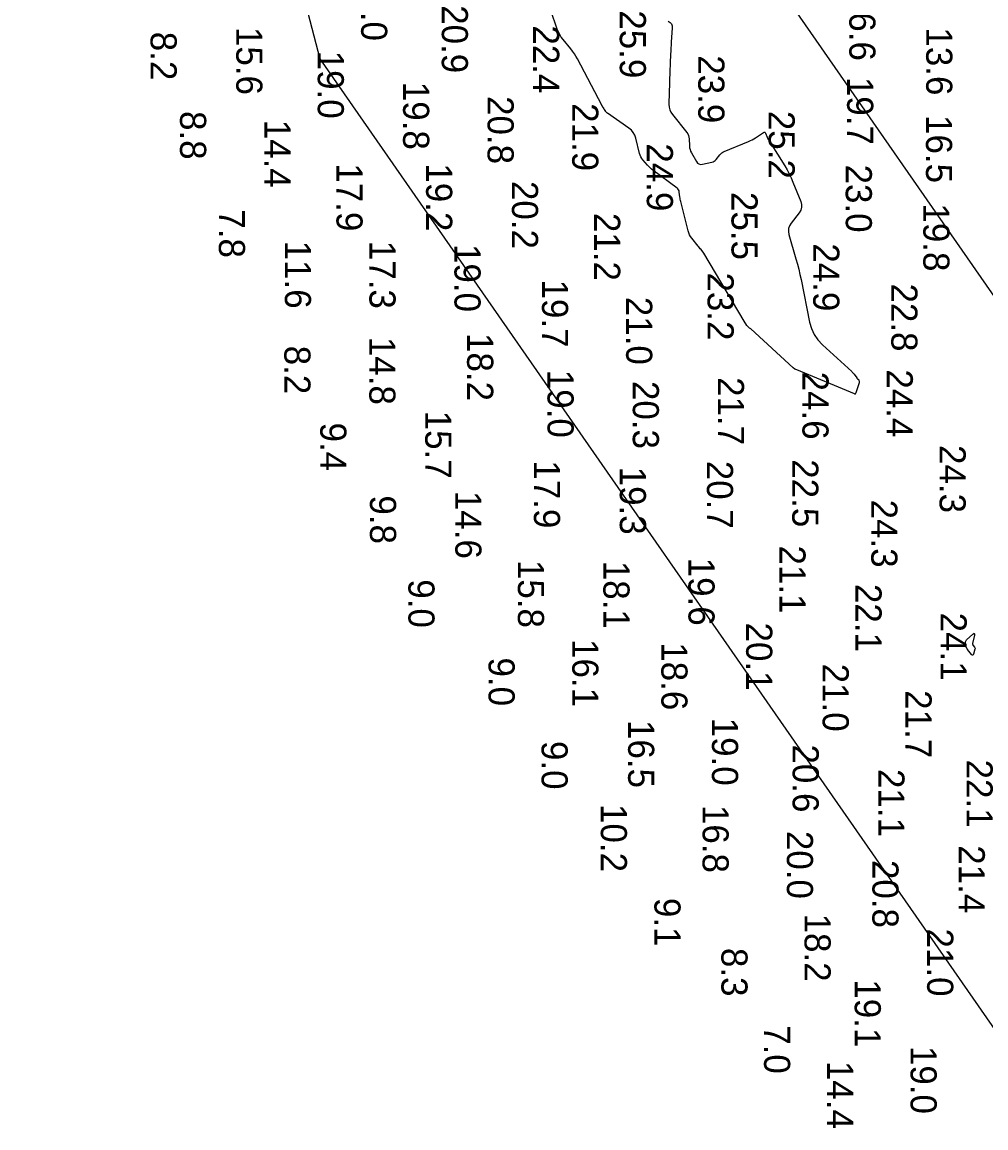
# Model space of a CAD drawing. Extents: x 1178573 to 1187098, y 693282 to 751751.
# Drawn here: x 1182495 to 1182956, y 742692 to 743221 of the extents above; entities that cross this region are included whole.
import ezdxf

# ---------------------------------------------------------------- set-up
doc = ezdxf.new("R2010")
doc.units = 0
for name, color, linetype in [('G-ANNO-PATT', 7, 'Continuous'), ('V-HYDS-MAJR', 7, 'Continuous'), ('V-HYDS-SOUN', 7, 'Continuous')]:
    doc.layers.add(name, color=color, linetype=linetype)

msp = doc.modelspace()

# ---------------------------------------------------------------- linework, layer by layer
at = {"layer": 'G-ANNO-PATT'}
for p, q in [((1182494.83, 743743.62), (1182637.36, 743203.34)), ((1183156.73, 742806.5), (1182821.74, 743288.49)), ((1182750.89, 743217.47), (1182747.88, 743226.33)), ((1182803.92, 743221.31), (1182804.85, 743220.72)), ((1182751.41, 743216.13), (1182750.89, 743217.47)), ((1182752.05, 743214.85), (1182751.41, 743216.13)), ((1182804.85, 743220.72), (1182805.49, 743219.96)), ((1182805.9, 743217.93), (1182805.45, 743211.39)), ((1182805.49, 743219.96), (1182805.84, 743219.03)), ((1182805.84, 743219.03), (1182805.9, 743217.93)), ((1182752.8, 743213.64), (1182752.05, 743214.85)), ((1182753.66, 743212.49), (1182752.8, 743213.64)), ((1182757.35, 743208.03), (1182753.66, 743212.49)), ((1182805.45, 743211.39), (1182805.36, 743209.9)), ((1182758.24, 743206.89), (1182757.35, 743208.03)), ((1182759.07, 743205.72), (1182758.24, 743206.89)), ((1182759.84, 743204.5), (1182759.07, 743205.72)), ((1182805.14, 743205.44), (1182804.66, 743192.78)), ((1182805.2, 743206.93), (1182805.14, 743205.44)), ((1182805.27, 743208.41), (1182805.2, 743206.93)), ((1182805.36, 743209.9), (1182805.27, 743208.41)), ((1182637.36, 743203.34), (1182974.41, 742718.39)), ((1182760.54, 743203.24), (1182759.84, 743204.5)), ((1182772.2, 743181.16), (1182760.54, 743203.24)), ((1182804.56, 743189.99), (1182804.51, 743188.59)), ((1182804.6, 743191.38), (1182804.56, 743189.99)), ((1182804.66, 743192.78), (1182804.6, 743191.38)), ((1182804.47, 743187.19), (1182804.31, 743181.59)), ((1182804.51, 743188.59), (1182804.47, 743187.19)), ((1182772.29, 743180.99), (1182772.2, 743181.16)), ((1182772.39, 743180.81), (1182772.29, 743180.99)), ((1182772.49, 743180.64), (1182772.39, 743180.81)), ((1182772.59, 743180.46), (1182772.49, 743180.64)), ((1182773.01, 743179.78), (1182772.59, 743180.46)), ((1182773.11, 743179.61), (1182773.01, 743179.78)), ((1182773.22, 743179.44), (1182773.11, 743179.61)), ((1182773.32, 743179.27), (1182773.22, 743179.44)), ((1182773.43, 743179.1), (1182773.32, 743179.27)), ((1182774.11, 743178.02), (1182773.43, 743179.1)), ((1182804.31, 743181.59), (1182804.38, 743180.23)), ((1182804.38, 743180.23), (1182804.69, 743178.95)), ((1182804.69, 743178.95), (1182805.22, 743177.74)), ((1182774.27, 743177.8), (1182774.11, 743178.02)), ((1182774.45, 743177.59), (1182774.27, 743177.8)), ((1182774.65, 743177.4), (1182774.45, 743177.59)), ((1182774.87, 743177.24), (1182774.65, 743177.4)), ((1182785.17, 743170.15), (1182774.87, 743177.24)), ((1182805.22, 743177.74), (1182805.98, 743176.61)), ((1182805.98, 743176.61), (1182812.83, 743168.1)), ((1182786.34, 743169.18), (1182785.17, 743170.15)), ((1182787.28, 743168.06), (1182786.34, 743169.18)), ((1182788, 743166.79), (1182787.28, 743168.06)), ((1182812.83, 743168.1), (1182813.3, 743167.4)), ((1182845.69, 743165.52), (1182849.57, 743168.11)), ((1182849.57, 743168.11), (1182849.9, 743168.27)), ((1182849.9, 743168.27), (1182850.18, 743168.27)), ((1182850.18, 743168.27), (1182850.4, 743168.11)), ((1182850.4, 743168.11), (1182850.57, 743167.78)), ((1182788.48, 743165.35), (1182788, 743166.79)), ((1182790.28, 743157.95), (1182788.48, 743165.35)), ((1182813.3, 743167.4), (1182813.65, 743166.66)), ((1182813.65, 743166.66), (1182813.88, 743165.87)), ((1182813.88, 743165.87), (1182813.99, 743165.04)), ((1182813.99, 743165.04), (1182814.15, 743161.6)), ((1182830.76, 743158.97), (1182842.45, 743163.79)), ((1182842.45, 743163.79), (1182843.3, 743164.16)), ((1182843.3, 743164.16), (1182844.11, 743164.57)), ((1182844.11, 743164.57), (1182844.91, 743165.02)), ((1182844.91, 743165.02), (1182845.69, 743165.52)), ((1182850.57, 743167.78), (1182851.25, 743165.85)), ((1182851.25, 743165.85), (1182851.35, 743165.61)), ((1182851.35, 743165.61), (1182851.45, 743165.39)), ((1182851.45, 743165.39), (1182851.57, 743165.17)), ((1182851.57, 743165.17), (1182851.71, 743164.96)), ((1182851.71, 743164.96), (1182852.28, 743164.12)), ((1182852.28, 743164.12), (1182852.42, 743163.91)), ((1182852.42, 743163.91), (1182852.56, 743163.7)), ((1182852.56, 743163.7), (1182852.7, 743163.49)), ((1182852.7, 743163.49), (1182852.83, 743163.28)), ((1182852.83, 743163.28), (1182859.71, 743152.13)), ((1182790.53, 743157.13), (1182790.28, 743157.95)), ((1182814.15, 743161.6), (1182814.24, 743160.75)), ((1182814.24, 743160.75), (1182814.43, 743159.93)), ((1182814.43, 743159.93), (1182814.71, 743159.14)), ((1182814.71, 743159.14), (1182815.09, 743158.38)), ((1182815.09, 743158.38), (1182817.46, 743154.18)), ((1182826.98, 743155.19), (1182828.66, 743157.36)), ((1182828.66, 743157.36), (1182829.1, 743157.87)), ((1182829.1, 743157.87), (1182829.6, 743158.3)), ((1182829.6, 743158.3), (1182830.16, 743158.67)), ((1182830.16, 743158.67), (1182830.76, 743158.97)), ((1182790.88, 743156.36), (1182790.53, 743157.13)), ((1182791.31, 743155.64), (1182790.88, 743156.36)), ((1182791.84, 743154.96), (1182791.31, 743155.64)), ((1182794.12, 743152.35), (1182791.84, 743154.96)), ((1182794.71, 743151.72), (1182794.12, 743152.35)), ((1182817.46, 743154.18), (1182818.01, 743153.45)), ((1182818.01, 743153.45), (1182818.67, 743153)), ((1182818.67, 743153), (1182819.46, 743152.8)), ((1182819.46, 743152.8), (1182820.36, 743152.88)), ((1182820.36, 743152.88), (1182824.79, 743153.82)), ((1182824.79, 743153.82), (1182825.43, 743154.02)), ((1182825.43, 743154.02), (1182826.01, 743154.31)), ((1182826.01, 743154.31), (1182826.52, 743154.7)), ((1182826.52, 743154.7), (1182826.98, 743155.19)), ((1182859.71, 743152.13), (1182860.82, 743150.25)), ((1182795.33, 743151.11), (1182794.71, 743151.72)), ((1182795.98, 743150.55), (1182795.33, 743151.11)), ((1182796.66, 743150.01), (1182795.98, 743150.55)), ((1182808.2, 743141.4), (1182796.66, 743150.01)), ((1182860.82, 743150.25), (1182861.84, 743148.32)), ((1182861.84, 743148.32), (1182862.79, 743146.35)), ((1182808.62, 743141.02), (1182808.2, 743141.4)), ((1182862.79, 743146.35), (1182863.65, 743144.34)), ((1182863.65, 743144.34), (1182867.38, 743135.07)), ((1182808.94, 743140.59), (1182808.62, 743141.02)), ((1182809.16, 743140.1), (1182808.94, 743140.59)), ((1182809.28, 743139.55), (1182809.16, 743140.1)), ((1182809.56, 743137.25), (1182809.28, 743139.55)), ((1182809.64, 743136.67), (1182809.56, 743137.25)), ((1182809.74, 743136.1), (1182809.64, 743136.67)), ((1182809.85, 743135.53), (1182809.74, 743136.1)), ((1182809.99, 743134.97), (1182809.85, 743135.53)), ((1182813.57, 743120.97), (1182809.99, 743134.97)), ((1182867.4, 743130.95), (1182866.63, 743129.68)), ((1182867.38, 743135.07), (1182867.77, 743133.65)), ((1182867.78, 743132.27), (1182867.4, 743130.95)), ((1182867.77, 743133.65), (1182867.78, 743132.27)), ((1182866.63, 743129.68), (1182862.78, 743124.72)), ((1182813.86, 743120.03), (1182813.57, 743120.97)), ((1182861.55, 743122.1), (1182861.46, 743120.7)), ((1182861.46, 743120.7), (1182861.73, 743119.22)), ((1182861.99, 743123.44), (1182861.55, 743122.1)), ((1182862.78, 743124.72), (1182861.99, 743123.44)), ((1182814.24, 743119.15), (1182813.86, 743120.03)), ((1182814.72, 743118.3), (1182814.24, 743119.15)), ((1182815.29, 743117.51), (1182814.72, 743118.3)), ((1182818.31, 743113.72), (1182815.29, 743117.51)), ((1182861.73, 743119.22), (1182865.12, 743107.56)), ((1182818.65, 743113.29), (1182818.31, 743113.72)), ((1182818.99, 743112.87), (1182818.65, 743113.29)), ((1182819.33, 743112.44), (1182818.99, 743112.87)), ((1182819.67, 743112.02), (1182819.33, 743112.44)), ((1182821.02, 743110.32), (1182819.67, 743112.02)), ((1182840.25, 743077.86), (1182821.02, 743110.32)), ((1182865.12, 743107.56), (1182865.8, 743105.11)), ((1182865.8, 743105.11), (1182866.43, 743102.64)), ((1182866.43, 743102.64), (1182867.01, 743100.17)), ((1182867.01, 743100.17), (1182867.54, 743097.67)), ((1182867.54, 743097.67), (1182871.61, 743077.37)), ((1182841.67, 743075.79), (1182840.25, 743077.86)), ((1182842.04, 743075.3), (1182841.67, 743075.79)), ((1182842.47, 743074.86), (1182842.04, 743075.3)), ((1182842.94, 743074.47), (1182842.47, 743074.86)), ((1182843.45, 743074.13), (1182842.94, 743074.47)), ((1182863.77, 743055.44), (1182843.45, 743074.13)), ((1182871.61, 743077.37), (1182872.48, 743074.27)), ((1182872.48, 743074.27), (1182873.8, 743071.42)), ((1182873.8, 743071.42), (1182875.56, 743068.82)), ((1182875.56, 743068.82), (1182877.77, 743066.47)), ((1182877.77, 743066.47), (1182891.77, 743053.73)), ((1182864.5, 743054.89), (1182863.77, 743055.44)), ((1182865.45, 743054.53), (1182864.5, 743054.89)), ((1182893.19, 743042.98), (1182865.45, 743054.53)), ((1182891.77, 743053.73), (1182892.07, 743053.44)), ((1182892.07, 743053.44), (1182892.36, 743053.14)), ((1182892.36, 743053.14), (1182892.63, 743052.82)), ((1182892.63, 743052.82), (1182892.88, 743052.48)), ((1182892.88, 743052.48), (1182894.21, 743050.65)), ((1182895.3, 743048.28), (1182893.7, 743043.48)), ((1182894.21, 743050.65), (1182894.29, 743050.54)), ((1182894.29, 743050.54), (1182894.38, 743050.44)), ((1182894.38, 743050.44), (1182894.48, 743050.35)), ((1182894.48, 743050.35), (1182894.58, 743050.27)), ((1182894.58, 743050.27), (1182895.01, 743049.95)), ((1182895.01, 743049.95), (1182895.11, 743049.87)), ((1182895.11, 743049.87), (1182895.18, 743049.77)), ((1182895.18, 743049.77), (1182895.24, 743049.65)), ((1182895.24, 743049.65), (1182895.26, 743049.53)), ((1182895.26, 743049.53), (1182895.35, 743048.88)), ((1182895.34, 743048.43), (1182895.3, 743048.28)), ((1182895.36, 743048.57), (1182895.34, 743048.43)), ((1182895.35, 743048.88), (1182895.37, 743048.72)), ((1182895.37, 743048.72), (1182895.36, 743048.57)), ((1182893.31, 743042.78), (1182893.19, 743042.98)), ((1182893.48, 743042.94), (1182893.31, 743042.78)), ((1182893.7, 743043.48), (1182893.48, 743042.94)), ((1182946.26, 742924.48), (1182946.34, 742924.8)), ((1182946.34, 742924.8), (1182946.49, 742925.1)), ((1182946.49, 742925.1), (1182946.72, 742925.37)), ((1182946.72, 742925.37), (1182949.67, 742928.1)), ((1182950.49, 742927.64), (1182949.65, 742923.56)), ((1182949.67, 742928.1), (1182950.15, 742928.47)), ((1182950.15, 742928.47), (1182950.45, 742928.52)), ((1182950.45, 742928.52), (1182950.56, 742928.24)), ((1182950.56, 742928.24), (1182950.49, 742927.64)), ((1182946.26, 742924.12), (1182946.26, 742924.48)), ((1182946.49, 742922.17), (1182946.26, 742924.12)), ((1182946.51, 742922.04), (1182946.49, 742922.17)), ((1182946.54, 742921.92), (1182946.51, 742922.04)), ((1182946.59, 742921.8), (1182946.54, 742921.92)), ((1182946.66, 742921.69), (1182946.59, 742921.8)), ((1182946.94, 742921.24), (1182946.66, 742921.69)), ((1182947.01, 742921.13), (1182946.94, 742921.24)), ((1182947.09, 742921.02), (1182947.01, 742921.13)), ((1182947.16, 742920.92), (1182947.09, 742921.02)), ((1182947.24, 742920.81), (1182947.16, 742920.92)), ((1182949.1, 742918.38), (1182947.24, 742920.81)), ((1182949.65, 742923.56), (1182949.63, 742923.32)), ((1182949.63, 742923.32), (1182949.66, 742923.08)), ((1182949.66, 742923.08), (1182949.74, 742922.86)), ((1182949.74, 742922.86), (1182949.89, 742922.66)), ((1182949.89, 742922.66), (1182950.57, 742921.87)), ((1182950.75, 742920.98), (1182950.01, 742918.55)), ((1182950.57, 742921.87), (1182950.7, 742921.67)), ((1182950.7, 742921.67), (1182950.78, 742921.45)), ((1182950.8, 742921.22), (1182950.75, 742920.98)), ((1182950.78, 742921.45), (1182950.8, 742921.22)), ((1182949.38, 742918.09), (1182949.1, 742918.38)), ((1182949.63, 742918.02), (1182949.38, 742918.09)), ((1182949.84, 742918.17), (1182949.63, 742918.02)), ((1182950.01, 742918.55), (1182949.84, 742918.17))]:
    msp.add_line(p, q, dxfattribs=at)
at = {"layer": 'V-HYDS-MAJR'}
msp.add_lwpolyline([(1182803.92, 743221.31), (1182804.85, 743220.72), (1182805.49, 743219.96), (1182805.84, 743219.03), (1182805.9, 743217.93), (1182805.45, 743211.39), (1182805.36, 743209.9), (1182805.27, 743208.41), (1182805.2, 743206.93), (1182805.14, 743205.44), (1182804.66, 743192.78), (1182804.6, 743191.38), (1182804.56, 743189.99), (1182804.51, 743188.59), (1182804.47, 743187.19), (1182804.31, 743181.59), (1182804.38, 743180.23), (1182804.69, 743178.95), (1182805.22, 743177.74), (1182805.98, 743176.61), (1182812.83, 743168.1), (1182813.3, 743167.4), (1182813.65, 743166.66), (1182813.88, 743165.87), (1182813.99, 743165.04), (1182814.15, 743161.6), (1182814.24, 743160.75), (1182814.43, 743159.93), (1182814.71, 743159.14), (1182815.09, 743158.38), (1182817.46, 743154.18), (1182818.01, 743153.45), (1182818.67, 743153), (1182819.46, 743152.8), (1182820.36, 743152.88), (1182824.79, 743153.82), (1182825.43, 743154.02), (1182826.01, 743154.31), (1182826.52, 743154.7), (1182826.98, 743155.19), (1182828.66, 743157.36), (1182829.1, 743157.87), (1182829.6, 743158.3), (1182830.16, 743158.67), (1182830.76, 743158.97), (1182842.45, 743163.79), (1182843.3, 743164.16), (1182844.11, 743164.57), (1182844.91, 743165.02), (1182845.69, 743165.52), (1182849.57, 743168.11), (1182849.9, 743168.27), (1182850.18, 743168.27), (1182850.4, 743168.11), (1182850.57, 743167.78), (1182851.25, 743165.85), (1182851.35, 743165.61), (1182851.45, 743165.39), (1182851.57, 743165.17), (1182851.71, 743164.96), (1182852.28, 743164.12), (1182852.42, 743163.91), (1182852.56, 743163.7), (1182852.7, 743163.49), (1182852.83, 743163.28), (1182859.71, 743152.13), (1182860.82, 743150.25), (1182861.84, 743148.32), (1182862.79, 743146.35), (1182863.65, 743144.34), (1182867.38, 743135.07), (1182867.77, 743133.65), (1182867.78, 743132.27), (1182867.4, 743130.95), (1182866.63, 743129.68), (1182862.78, 743124.72), (1182861.99, 743123.44), (1182861.55, 743122.1), (1182861.46, 743120.7), (1182861.73, 743119.22), (1182865.12, 743107.56), (1182865.8, 743105.11), (1182866.43, 743102.64), (1182867.01, 743100.17), (1182867.54, 743097.67), (1182871.61, 743077.37), (1182872.48, 743074.27), (1182873.8, 743071.42), (1182875.56, 743068.82), (1182877.77, 743066.47), (1182891.77, 743053.73), (1182892.07, 743053.44), (1182892.36, 743053.14), (1182892.63, 743052.82), (1182892.88, 743052.48), (1182894.21, 743050.65), (1182894.29, 743050.54), (1182894.38, 743050.44), (1182894.48, 743050.35), (1182894.58, 743050.27), (1182895.01, 743049.95), (1182895.11, 743049.87), (1182895.18, 743049.77), (1182895.24, 743049.65), (1182895.26, 743049.53), (1182895.35, 743048.88), (1182895.37, 743048.72), (1182895.36, 743048.57), (1182895.34, 743048.43), (1182895.3, 743048.28), (1182893.7, 743043.48), (1182893.48, 743042.94), (1182893.31, 743042.78), (1182893.19, 743042.98), (1182865.45, 743054.53), (1182864.5, 743054.89), (1182863.77, 743055.44), (1182843.45, 743074.13), (1182842.94, 743074.47), (1182842.47, 743074.86), (1182842.04, 743075.3), (1182841.67, 743075.79), (1182840.25, 743077.86), (1182821.02, 743110.32), (1182819.67, 743112.02), (1182819.33, 743112.44), (1182818.99, 743112.87), (1182818.65, 743113.29), (1182818.31, 743113.72), (1182815.29, 743117.51), (1182814.72, 743118.3), (1182814.24, 743119.15), (1182813.86, 743120.03), (1182813.57, 743120.97), (1182809.99, 743134.97), (1182809.85, 743135.53), (1182809.74, 743136.1), (1182809.64, 743136.67), (1182809.56, 743137.25), (1182809.28, 743139.55), (1182809.16, 743140.1), (1182808.94, 743140.59), (1182808.62, 743141.02), (1182808.2, 743141.4), (1182796.66, 743150.01), (1182795.98, 743150.55), (1182795.33, 743151.11), (1182794.71, 743151.72), (1182794.12, 743152.35), (1182791.84, 743154.96), (1182791.31, 743155.64), (1182790.88, 743156.36), (1182790.53, 743157.13), (1182790.28, 743157.95), (1182788.48, 743165.35), (1182788, 743166.79), (1182787.28, 743168.06), (1182786.34, 743169.18), (1182785.17, 743170.15), (1182774.87, 743177.24), (1182774.65, 743177.4), (1182774.45, 743177.59), (1182774.27, 743177.8), (1182774.11, 743178.02), (1182773.43, 743179.1), (1182773.32, 743179.27), (1182773.22, 743179.44), (1182773.11, 743179.61), (1182773.01, 743179.78), (1182772.59, 743180.46), (1182772.49, 743180.64), (1182772.39, 743180.81), (1182772.29, 743180.99), (1182772.2, 743181.16), (1182760.54, 743203.24), (1182759.84, 743204.5), (1182759.07, 743205.72), (1182758.24, 743206.89), (1182757.35, 743208.03), (1182753.66, 743212.49), (1182752.8, 743213.64), (1182752.05, 743214.85), (1182751.41, 743216.13), (1182750.89, 743217.47), (1182747.88, 743226.33)], dxfattribs=at)
msp.add_lwpolyline([(1182946.34, 742924.8), (1182946.49, 742925.1), (1182946.72, 742925.37), (1182949.67, 742928.1), (1182950.15, 742928.47), (1182950.45, 742928.52), (1182950.56, 742928.24), (1182950.49, 742927.64), (1182949.65, 742923.56), (1182949.63, 742923.32), (1182949.66, 742923.08), (1182949.74, 742922.86), (1182949.89, 742922.66), (1182950.57, 742921.87), (1182950.7, 742921.67), (1182950.78, 742921.45), (1182950.8, 742921.22), (1182950.75, 742920.98), (1182950.01, 742918.55), (1182949.84, 742918.17), (1182949.63, 742918.02), (1182949.38, 742918.09), (1182949.1, 742918.38), (1182947.24, 742920.81), (1182947.16, 742920.92), (1182947.09, 742921.02), (1182947.01, 742921.13), (1182946.94, 742921.24), (1182946.66, 742921.69), (1182946.59, 742921.8), (1182946.54, 742921.92), (1182946.51, 742922.04), (1182946.49, 742922.17), (1182946.26, 742924.12), (1182946.26, 742924.48)], close=True, dxfattribs=at)

# ---------------------------------------------------------------- texts
at = {"layer": 'V-HYDS-SOUN'}
for s, p in [('20.0 ', (1182657.05, 743244.37)), ('16.6 ', (1182890.64, 743234.84)), ('20.9 ', (1182695.64, 743228.94)), ('25.9 ', (1182780.81, 743226.48)), ('8.2', (1182556.3, 743216.24)), ('15.6 ', (1182597.3, 743218.54)), ('22.4 ', (1182739.33, 743219.27)), ('13.6 ', (1182927.42, 743218.31)), ('19.0 ', (1182636.28, 743207.16)), ('23.9 ', (1182818.37, 743204.99)), ('19.8 ', (1182677.13, 743192.29)), ('19.7 ', (1182889.59, 743194.65)), ('20.8 ', (1182717.55, 743185.47)), ('21.9 ', (1182758.04, 743182.09)), ('8.8', (1182570.41, 743178.3)), ('25.2 ', (1182852.02, 743178.41)), ('16.5 ', (1182927.33, 743176.39)), ('14.4 ', (1182610.79, 743174.13)), ('24.9 ', (1182793.74, 743162.86)), ('17.9 ', (1182645.24, 743153.28)), ('19.2 ', (1182688.14, 743153.28)), ('23.0 ', (1182888.93, 743152.7)), ('20.2 ', (1182729.21, 743144.88)), ('25.5 ', (1182834.25, 743139.61)), ('19.8 ', (1182926.05, 743134.12)), ('7.8', (1182588.98, 743131.29)), ('21.2 ', (1182768.52, 743129.59)), ('11.6 ', (1182620.56, 743116.31)), ('17.3 ', (1182661.02, 743116.24)), ('19.0 ', (1182701.7, 743114.71)), ('24.9 ', (1182873.36, 743115.03)), ('23.2 ', (1182822.82, 743101.11)), ('19.7 ', (1182743.59, 743097.74)), ('22.8 ', (1182910.73, 743095.83)), ('21.0 ', (1182783.85, 743089.45)), ('14.8 ', (1182660.96, 743070.31)), ('18.2 ', (1182707.76, 743072.14)), ('8.2', (1182620.31, 743066.08)), ('19.0 ', (1182746.22, 743054.54)), ('24.6 ', (1182868.2, 743053.68)), ('24.4 ', (1182908.52, 743054.74)), ('20.3 ', (1182787.03, 743049.21)), ('21.7 ', (1182827.75, 743051.05)), ('15.7 ', (1182687.72, 743034.98)), ('9.4', (1182637.5, 743029.31)), ('24.3 ', (1182933.82, 743018.57)), ('17.9 ', (1182739.73, 743011.22)), ('20.7 ', (1182822.5, 743011.03)), ('22.5 ', (1182863.32, 743011.76)), ('19.3 ', (1182780.83, 743008.2)), ('9.8', (1182661.29, 742994.47)), ('14.6 ', (1182702.12, 742996.65)), ('24.3 ', (1182901.14, 742992.46)), ('21.1 ', (1182857.19, 742970.53)), ('15.8 ', (1182732.06, 742963.62)), ('18.1 ', (1182772.97, 742963.18)), ('19.6 ', (1182813.67, 742964.67)), ('9.0', (1182679.66, 742954.34)), ('22.1 ', (1182893.57, 742952.13)), ('24.1 ', (1182934.29, 742938.41)), ('20.1 ', (1182841.28, 742933.66)), ('16.1 ', (1182758.08, 742925.75)), ('18.6 ', (1182800.71, 742924.22)), ('9.0', (1182718.01, 742916.94)), ('21.0 ', (1182877.88, 742913.99)), ('21.7 ', (1182917.51, 742901.32)), ('16.5 ', (1182784.81, 742887.05)), ('19.0 ', (1182824.93, 742888.14)), ('9.0', (1182743.37, 742877.01)), ('20.6 ', (1182863.51, 742875.36)), ('22.1 ', (1182946.72, 742868.11)), ('21.1 ', (1182904.53, 742863.61)), ('10.2 ', (1182771.73, 742846.85)), ('16.8 ', (1182820.41, 742846.43)), ('20.0 ', (1182860.75, 742834)), ('21.4 ', (1182942.97, 742827.15)), ('20.8 ', (1182901.67, 742820.11)), ('9.1', (1182797.38, 742801.95)), ('18.2 ', (1182869.21, 742794.45)), ('21.0 ', (1182927.88, 742787.32)), ('8.3', (1182829.43, 742778.03)), ('19.1 ', (1182893.21, 742762.99)), ('7.0', (1182849.84, 742741.06)), ('19.0 ', (1182919.94, 742731.15)), ('14.4 ', (1182879.98, 742723.99))]:
    msp.add_text(s, height=12.5, rotation=270, dxfattribs=at).set_placement(p)

doc.saveas('drawing.dxf')
